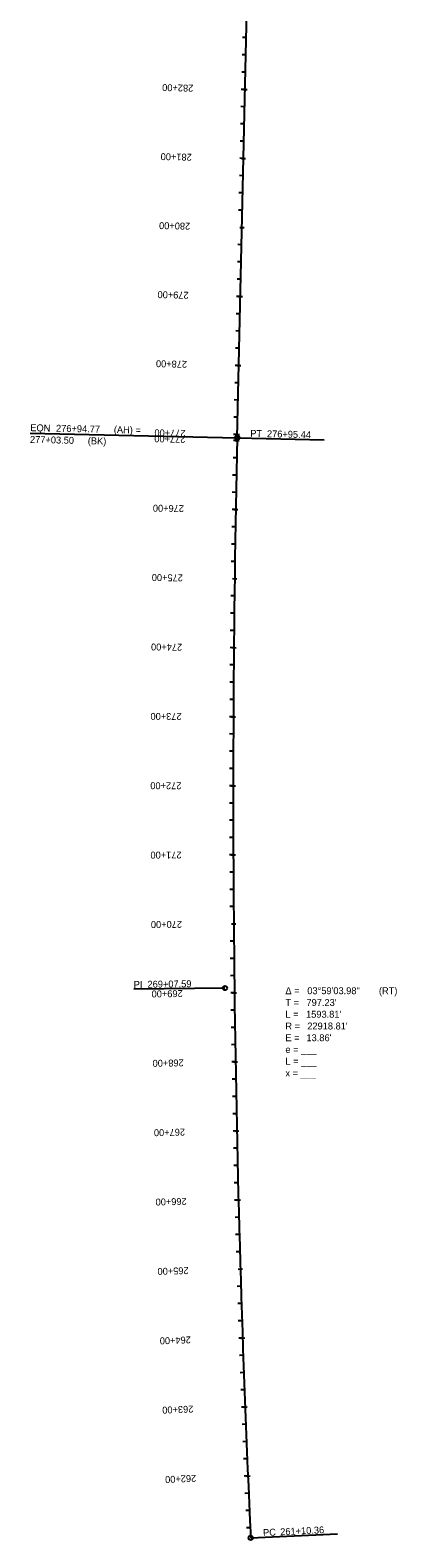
# Model space of a CAD drawing. Extents: x 23417911 to 23421158, y 6737892 to 6791804.
# Drawn here: x 23417911 to 23418443, y 6752584 to 6754767 of the extents above; entities that cross this region are included whole.
import ezdxf

# ---------------------------------------------------------------- set-up
doc = ezdxf.new("R2010")
doc.units = 0
for name, color, linetype in [('Alignment', 7, 'Continuous'), ('TextAlignment', 7, 'Continuous'), ('TextAlignmentLrg', 7, 'Continuous'), ('TextAlignmentSml', 7, 'Continuous')]:
    doc.layers.add(name, color=color, linetype=linetype)

msp = doc.modelspace()

# ---------------------------------------------------------------- linework, layer by layer
at = {"layer": 'Alignment'}
msp.add_line((23418211.4, 6754177.1), (23418252, 6755979.4), dxfattribs=at)
msp.add_line((23418211.4, 6754177.1), (23418252, 6755979.4), dxfattribs=at)
msp.add_arc((23441124.4, 6753661.5), 22918.8, 178.71097, 182.69541, dxfattribs=at)
msp.add_arc((23441124.4, 6753661.5), 22918.8, 178.71097, 182.69541, dxfattribs=at)
at = {"layer": 'TextAlignment'}
for p, q in [((23418211.4, 6754176.4), (23417911.5, 6754183.1)), ((23418211.4, 6754177.1), (23418337.4, 6754174.2)), ((23418337.4, 6754174.2), (23418337.4, 6754174.2)), ((23418193.5, 6753380), (23418061.5, 6753378.4)), ((23418061.5, 6753378.4), (23418061.5, 6753378.4)), ((23418231, 6752583.7), (23418356.8, 6752589.6)), ((23418356.8, 6752589.6), (23418356.8, 6752589.6))]:
    msp.add_line(p, q, dxfattribs=at)
for centre, radius in [((23418211.4, 6754177.1), 3.12), ((23418211.4, 6754176.4), 2.67), ((23418193.5, 6753380), 3.12), ((23418231, 6752583.7), 3.12)]:
    msp.add_circle(centre, radius, dxfattribs=at)
at = {"layer": 'TextAlignmentLrg'}
for p, q in [((23418222.8, 6754681.5), (23418217.3, 6754681.6)), ((23418220.5, 6754581.5), (23418215.1, 6754581.7)), ((23418215.2, 6754481.6), (23418221.3, 6754481.5)), ((23418216, 6754381.6), (23418210.6, 6754381.7)), ((23418213.8, 6754281.6), (23418208.3, 6754281.7)), ((23418211.3, 6754172.9), (23418205.9, 6754173)), ((23418211.5, 6754181.6), (23418206.1, 6754181.8)), ((23418209.3, 6754072.9), (23418203.9, 6754073)), ((23418204.7, 6753973), (23418210.8, 6753972.9)), ((23418206.6, 6753872.9), (23418201.1, 6753873)), ((23418205.9, 6753772.9), (23418200.4, 6753773)), ((23418205.6, 6753672.9), (23418200.2, 6753672.9)), ((23418205.8, 6753572.9), (23418200.3, 6753572.9)), ((23418203.3, 6753472.9), (23418209.5, 6753473)), ((23418207.4, 6753373), (23418202, 6753372.9)), ((23418208.9, 6753273), (23418203.5, 6753272.9)), ((23418210.8, 6753173), (23418205.4, 6753172.9)), ((23418213.2, 6753073), (23418207.7, 6753072.9)), ((23418212.9, 6752973), (23418219, 6752973.1)), ((23418219.2, 6752873.1), (23418213.7, 6752872.9)), ((23418222.9, 6752773.2), (23418217.4, 6752773)), ((23418226.9, 6752673.3), (23418221.5, 6752673))]:
    msp.add_line(p, q, dxfattribs=at)
at = {"layer": 'TextAlignmentSml'}
for p, q in [((23418224.5, 6754756.5), (23418219, 6754756.6)), ((23418223.9, 6754731.5), (23418218.4, 6754731.6)), ((23418223.3, 6754706.5), (23418217.9, 6754706.6)), ((23418219.7, 6754681.6), (23418225.8, 6754681.4)), ((23418222.2, 6754656.5), (23418216.8, 6754656.6)), ((23418221.7, 6754631.5), (23418216.2, 6754631.6)), ((23418221.1, 6754606.5), (23418215.6, 6754606.6)), ((23418217.5, 6754581.6), (23418223.6, 6754581.5)), ((23418220, 6754556.5), (23418214.5, 6754556.7)), ((23418219.4, 6754531.5), (23418213.9, 6754531.7)), ((23418218.8, 6754506.5), (23418213.4, 6754506.7)), ((23418215.2, 6754481.6), (23418221.3, 6754481.5)), ((23418217.7, 6754456.6), (23418212.3, 6754456.7)), ((23418217.2, 6754431.6), (23418211.7, 6754431.7)), ((23418216.6, 6754406.6), (23418211.1, 6754406.7)), ((23418213, 6754381.6), (23418219.1, 6754381.5)), ((23418215.5, 6754356.6), (23418210, 6754356.7)), ((23418214.9, 6754331.6), (23418209.4, 6754331.7)), ((23418214.3, 6754306.6), (23418208.9, 6754306.7)), ((23418210.7, 6754281.7), (23418216.8, 6754281.5)), ((23418213.2, 6754256.6), (23418207.8, 6754256.7)), ((23418212.7, 6754231.6), (23418207.2, 6754231.7)), ((23418212.1, 6754206.6), (23418206.6, 6754206.7)), ((23418208.3, 6754173), (23418214.4, 6754172.8)), ((23418208.5, 6754181.7), (23418214.6, 6754181.6)), ((23418210.8, 6754147.9), (23418205.3, 6754148)), ((23418210.3, 6754122.9), (23418204.8, 6754123)), ((23418209.8, 6754097.9), (23418204.3, 6754098)), ((23418206.3, 6754073), (23418212.4, 6754072.9)), ((23418208.9, 6754047.9), (23418203.4, 6754048)), ((23418208.5, 6754022.9), (23418203, 6754023)), ((23418208.1, 6753997.9), (23418202.6, 6753998)), ((23418204.7, 6753973), (23418210.8, 6753972.9)), ((23418207.4, 6753947.9), (23418202, 6753948)), ((23418207.1, 6753922.9), (23418201.7, 6753923)), ((23418206.8, 6753897.9), (23418201.4, 6753898)), ((23418203.5, 6753873), (23418209.7, 6753872.9)), ((23418206.4, 6753847.9), (23418200.9, 6753848)), ((23418206.2, 6753822.9), (23418200.7, 6753823)), ((23418206, 6753797.9), (23418200.6, 6753798)), ((23418202.8, 6753773), (23418209, 6753772.9)), ((23418205.8, 6753747.9), (23418200.3, 6753748)), ((23418205.7, 6753722.9), (23418200.3, 6753723)), ((23418205.7, 6753697.9), (23418200.2, 6753698)), ((23418202.6, 6753672.9), (23418208.7, 6753672.9)), ((23418205.6, 6753647.9), (23418200.2, 6753647.9)), ((23418205.7, 6753622.9), (23418200.2, 6753622.9)), ((23418205.7, 6753597.9), (23418200.3, 6753597.9)), ((23418202.7, 6753572.9), (23418208.9, 6753573)), ((23418205.9, 6753547.9), (23418200.5, 6753547.9)), ((23418206, 6753522.9), (23418200.6, 6753522.9)), ((23418206.2, 6753497.9), (23418200.8, 6753497.9)), ((23418203.3, 6753472.9), (23418209.5, 6753473)), ((23418206.6, 6753447.9), (23418201.2, 6753447.9)), ((23418206.9, 6753422.9), (23418201.4, 6753422.9)), ((23418207.1, 6753398), (23418201.7, 6753397.9)), ((23418204.4, 6753372.9), (23418210.5, 6753373)), ((23418207.8, 6753348), (23418202.3, 6753347.9)), ((23418208.1, 6753323), (23418202.7, 6753322.9)), ((23418208.5, 6753298), (23418203.1, 6753297.9)), ((23418205.9, 6753272.9), (23418212, 6753273)), ((23418209.4, 6753248), (23418203.9, 6753247.9)), ((23418209.8, 6753223), (23418204.4, 6753222.9)), ((23418210.3, 6753198), (23418204.9, 6753197.9)), ((23418207.8, 6753172.9), (23418213.9, 6753173)), ((23418211.4, 6753148), (23418205.9, 6753147.9)), ((23418212, 6753123), (23418206.5, 6753122.9)), ((23418212.6, 6753098), (23418207.1, 6753097.9)), ((23418210.1, 6753072.9), (23418216.2, 6753073.1)), ((23418213.8, 6753048), (23418208.4, 6753047.9)), ((23418214.5, 6753023), (23418209.1, 6753022.9)), ((23418215.2, 6752998), (23418209.8, 6752997.9)), ((23418212.9, 6752973), (23418219, 6752973.1)), ((23418216.7, 6752948.1), (23418211.3, 6752947.9)), ((23418217.5, 6752923.1), (23418212.1, 6752922.9)), ((23418218.3, 6752898.1), (23418212.9, 6752897.9)), ((23418216.1, 6752873), (23418222.3, 6752873.2)), ((23418220.1, 6752848.1), (23418214.6, 6752847.9)), ((23418221, 6752823.1), (23418215.5, 6752822.9)), ((23418221.9, 6752798.1), (23418216.4, 6752797.9)), ((23418219.8, 6752773), (23418225.9, 6752773.3)), ((23418223.8, 6752748.2), (23418218.4, 6752748)), ((23418224.8, 6752723.2), (23418219.4, 6752723)), ((23418225.9, 6752698.2), (23418220.4, 6752698)), ((23418223.9, 6752673.1), (23418230, 6752673.4)), ((23418228, 6752648.3), (23418222.6, 6752648)), ((23418229.2, 6752623.3), (23418223.7, 6752623.1)), ((23418230.3, 6752598.3), (23418224.8, 6752598.1))]:
    msp.add_line(p, q, dxfattribs=at)

# ---------------------------------------------------------------- texts
at = {"layer": 'TextAlignment'}
for s, rotation, p in [('EQN ', 358.7126, (23417911.6, 6754186.6)), ('276+94.77', 358.7126, (23417948.9, 6754185.8)), ('277+03.50', 358.7126, (23417911.2, 6754169.6)), ('(BK)', 358.7126, (23417994.9, 6754167.7)), ('(AH) = ', 358.7126, (23418032.6, 6754183.9)), ('PT', 358.711, (23418230.2, 6754178.3)), ('276+95.44', 358.711, (23418254.4, 6754177.8)), ('PI ', 0.7032, (23418061.5, 6753380.1)), ('269+07.59', 0.7032, (23418081.5, 6753380.4)), ('PC', 2.6954, (23418249, 6752586.2)), ('261+10.36', 2.6954, (23418273.9, 6752587.4))]:
    msp.add_text(s, height=10.02, rotation=rotation, dxfattribs=at).set_placement(p)
for s, p in [('Δ = ', (23418281.2, 6753371.1)), ('03°59\'03.98"', (23418312.9, 6753371.1)), (' (RT)', (23418412.9, 6753371.1)), ('T = ', (23418281.2, 6753354.1)), ('L = ', (23418281.2, 6753337)), ("1593.81'", (23418311.1, 6753337)), ("797.23'", (23418311.7, 6753354.1)), ('R = ', (23418281.2, 6753320)), ("22918.81'", (23418312.9, 6753320)), ('E = ', (23418281.2, 6753303)), ("13.86'", (23418311.7, 6753303)), ('e = ___ ', (23418281.2, 6753285.9)), ('L = ___', (23418281.2, 6753268.9)), ('x = ___', (23418281.2, 6753251.9))]:
    msp.add_text(s, height=10.02, dxfattribs=at).set_placement(p)
at = {"layer": 'TextAlignmentLrg'}
for s, rotation, p in [('280+00', 178.711, (23418143.4, 6754488.3)), ('275+00', 179.2214, (23418132.8, 6753979)), ('270+00', 180.4714, (23418131.4, 6753477.3)), ('265+00', 181.7213, (23418140.9, 6752975.8))]:
    msp.add_text(s, height=10.02, rotation=rotation, dxfattribs=at).set_placement(p)
at = {"layer": 'TextAlignmentSml'}
for s, rotation, p in [('282+00', 178.711, (23418147.9, 6754688.2)), ('281+00', 178.711, (23418145.7, 6754588.2)), ('280+00', 178.711, (23418143.4, 6754488.3)), ('279+00', 178.711, (23418141.2, 6754388.3)), ('278+00', 178.711, (23418138.9, 6754288.3)), ('277+00', 178.7214, (23418136.5, 6754179.6)), ('277+00', 178.711, (23418136.7, 6754188.3)), ('276+00', 178.9714, (23418134.4, 6754079.3)), ('275+00', 179.2214, (23418132.8, 6753979)), ('274+00', 179.4714, (23418131.7, 6753878.6)), ('273+00', 179.7214, (23418130.9, 6753778.3)), ('272+00', 179.9714, (23418130.6, 6753678)), ('271+00', 180.2214, (23418130.8, 6753577.7)), ('270+00', 180.4714, (23418131.4, 6753477.3)), ('269+00', 180.7214, (23418132.4, 6753377)), ('268+00', 180.9713, (23418133.8, 6753276.7)), ('267+00', 181.2213, (23418135.7, 6753176.4)), ('266+00', 181.4713, (23418138.1, 6753076.1)), ('265+00', 181.7213, (23418140.9, 6752975.8)), ('264+00', 181.9713, (23418144.1, 6752875.5)), ('263+00', 182.2213, (23418147.7, 6752775.3)), ('262+00', 182.4713, (23418151.8, 6752675))]:
    msp.add_text(s, height=10.02, rotation=rotation, dxfattribs=at).set_placement(p)

doc.saveas('drawing.dxf')
